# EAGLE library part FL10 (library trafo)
TRANSFORMER 2 primary winding, 2 secondary windings, mounting holes BLOCK
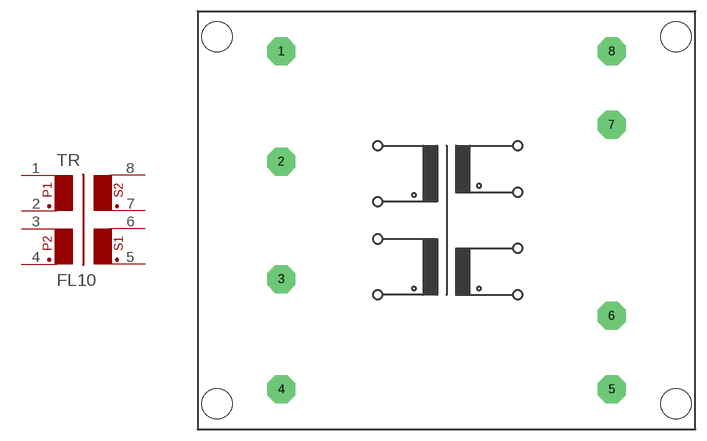
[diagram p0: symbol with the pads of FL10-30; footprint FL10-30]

Designator prefix TR

## FL10  [FL10-30]
1  1  pas
2  2  pas
3  3  pas
4  4  pas
5  5  pas
6  6  pas
7  7  pas
8  8  pas

## Footprint FL10-30 (pad centres in mm)
TRANSFORMER 2 primary winding, 2 secondary windings, mounting holes
drill 1.194 pad 3.81 octagon: 1 -22.504,23.012; 2 -22.504,8.001; 3 -22.504,-8.001; 4 -22.504,-23.012; 5 22.504,-23.012; 6 22.504,-13.005; 7 22.504,13.005; 8 22.504,23.012
hole 4.115 at -31.267,24.994
hole 4.115 at 31.267,24.994
hole 4.115 at 31.267,-24.994
hole 4.115 at -31.267,-24.994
